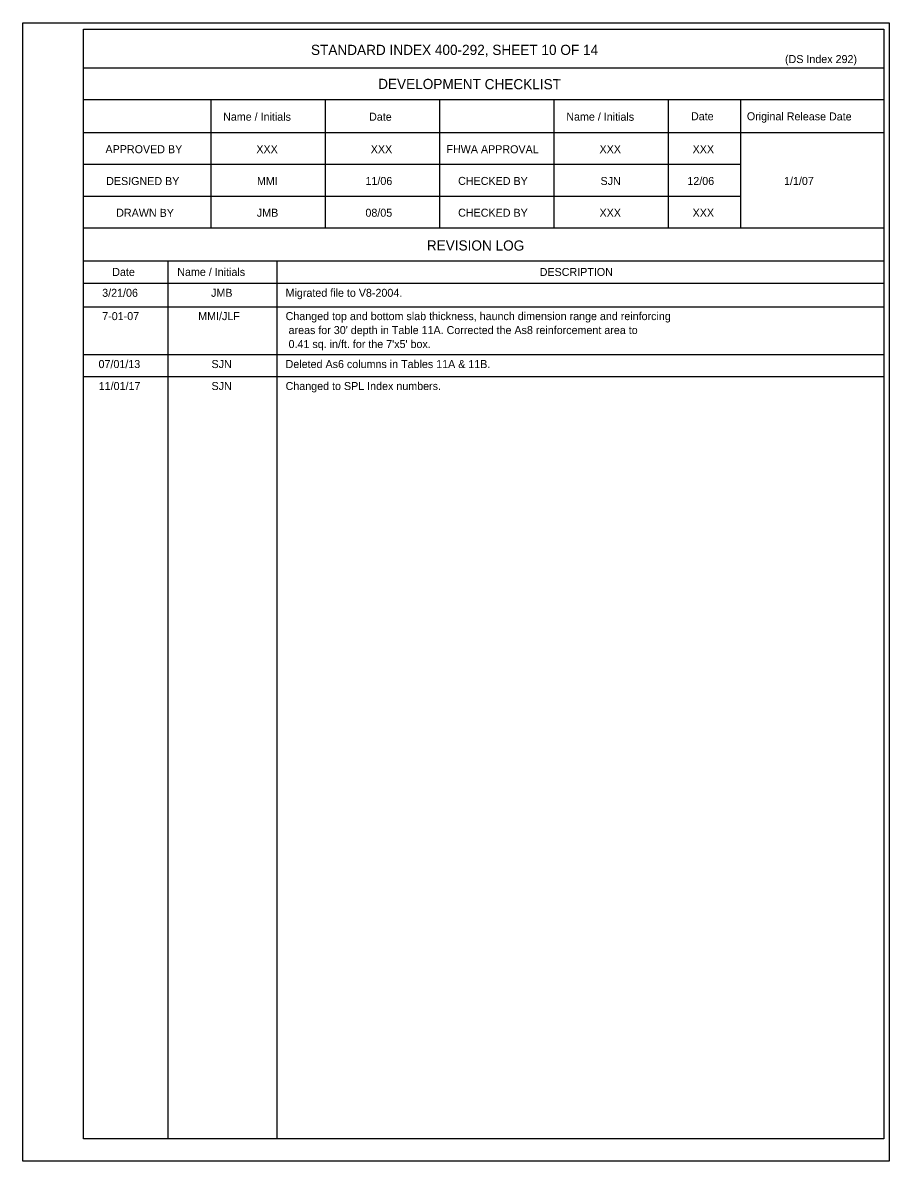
# Model space of a CAD drawing. Extents: x 10342.77 to 10344.98, y 76371.51 to 76372.62.
# Drawn here: x 10344.301 to 10344.983, y 76371.667 to 76372.563 of the extents above; entities that cross this region are included whole.
import ezdxf

# ---------------------------------------------------------------- set-up
doc = ezdxf.new("R2010")
doc.units = 0
for name, color, linetype in [('AdhocPoint_dp', 7, 'Continuous'), ('Border', 7, 'Continuous'), ('PlotBorder_dp', 7, 'Continuous')]:
    doc.layers.add(name, color=color, linetype=linetype)

msp = doc.modelspace()

# ---------------------------------------------------------------- linework, layer by layer
at = {"layer": 'Border'}
for p, q in [((10344.97841, 76372.52706), (10344.34883, 76372.52706)), ((10344.97841, 76372.50206), (10344.34883, 76372.50206)), ((10344.44883, 76372.50206), (10344.44883, 76372.40119)), ((10344.53883, 76372.50206), (10344.53883, 76372.40119)), ((10344.62883, 76372.50206), (10344.62883, 76372.40119)), ((10344.71883, 76372.50206), (10344.71883, 76372.40119)), ((10344.80883, 76372.50206), (10344.80883, 76372.40119)), ((10344.86554, 76372.50206), (10344.86554, 76372.40119)), ((10344.97841, 76372.47619), (10344.34883, 76372.47619)), ((10344.86554, 76372.45119), (10344.34883, 76372.45119)), ((10344.86554, 76372.42619), (10344.34883, 76372.42619)), ((10344.97841, 76372.40119), (10344.34883, 76372.40119)), ((10344.97841, 76372.37532), (10344.34883, 76372.37532)), ((10344.41509, 76372.37532), (10344.41509, 76371.68449)), ((10344.50078, 76372.37532), (10344.50078, 76371.68449)), ((10344.97841, 76372.3577), (10344.34883, 76372.3577)), ((10344.301, 76371.66695), (10344.301, 76371.66695))]:
    msp.add_line(p, q, dxfattribs=at)
for points in [[(10344.301, 76372.56278), (10344.98267, 76372.56278), (10344.98267, 76371.66695), (10344.301, 76371.66695)], [(10344.34884, 76372.5577), (10344.97841, 76372.5577), (10344.97841, 76371.68449), (10344.34884, 76371.68449)]]:
    msp.add_lwpolyline(points, close=True, dxfattribs=at)
at = {"layer": 'PlotBorder_dp'}
for p, q in [((10344.34884, 76372.33937), (10344.97841, 76372.33937)), ((10344.34884, 76372.30164), (10344.97841, 76372.30164)), ((10344.34884, 76372.28435), (10344.97841, 76372.28435))]:
    msp.add_line(p, q, dxfattribs=at)

# ---------------------------------------------------------------- texts
at = {"layer": 'AdhocPoint_dp'}
for s, height, p in [('STANDARD INDEX 400-292, SHEET 10 OF 14', 0.008, (10344.52773, 76372.53745)), ('(DS Index 292)', 0.0063, (10344.90067, 76372.53106)), ('XXX', 0.0063, (10344.48477, 76372.46015)), ('XXX', 0.0063, (10344.57477, 76372.46015)), ('XXX', 0.0063, (10344.75476, 76372.46015)), ('XXX', 0.0063, (10344.82799, 76372.46015)), ('MMI', 0.0063, (10344.48526, 76372.43515)), ('11/06', 0.0063, (10344.57062, 76372.43515)), ('SJN', 0.0063, (10344.75553, 76372.43515)), ('12/06', 0.0063, (10344.82385, 76372.43515)), ('1/1/07', 0.0063, (10344.89992, 76372.43515)), ('JMB', 0.0063, (10344.48517, 76372.41015)), ('08/05', 0.0063, (10344.57058, 76372.41015)), ('XXX', 0.0063, (10344.75476, 76372.41015)), ('XXX', 0.0063, (10344.82799, 76372.41015)), ('DESCRIPTION', 0.0063, (10344.70769, 76372.36354)), ('3/21/06', 0.0063, (10344.36349, 76372.34714)), ('JMB', 0.0063, (10344.44913, 76372.34714)), ('Migrated file to V8-2004.', 0.0063, (10344.50777, 76372.34714)), ('MMI/JLF', 0.0063, (10344.439, 76372.3288)), ('Changed top and bottom slab thickness, haunch dimension range and reinforcing ', 0.0063, (10344.50778, 76372.3288)), ('7-01-07', 0.0063, (10344.36351, 76372.3288)), (" areas for 30' depth in Table 11A. Corrected the As8 reinforcement area to ", 0.0063, (10344.50778, 76372.31782)), (" 0.41 sq. in/ft. for the 7'x5' box.", 0.0063, (10344.50778, 76372.30683)), ('07/01/13', 0.0063, (10344.3606, 76372.29108)), ('SJN', 0.0063, (10344.4495, 76372.29108)), ('Deleted As6 columns in Tables 11A & 11B.', 0.0063, (10344.50778, 76372.29108)), ('11/01/17', 0.0063, (10344.36075, 76372.27379)), ('SJN', 0.0063, (10344.4495, 76372.27379)), ('Changed to SPL Index numbers.', 0.0063, (10344.50778, 76372.27379))]:
    msp.add_text(s, height=height, dxfattribs=at).set_placement(p)
for s, height, p in [('DEVELOPMENT CHECKLIST', 0.008, (10344.58057, 76372.51071)), ('Name / Initials', 0.0063, (10344.4586, 76372.48578)), ('Date', 0.0063, (10344.57343, 76372.48573)), ('Name / Initials', 0.0063, (10344.7286, 76372.48578)), ('Date', 0.0063, (10344.82671, 76372.48609)), ('Original Release Date', 0.0063, (10344.87066, 76372.48608)), ('APPROVED BY', 0.0063, (10344.36607, 76372.46021)), ('FHWA APPROVAL', 0.0063, (10344.6343, 76372.46021)), ('DESIGNED BY', 0.0063, (10344.3666, 76372.43515)), ('CHECKED BY', 0.0063, (10344.64351, 76372.43521)), ('DRAWN BY', 0.0063, (10344.3745, 76372.41015)), ('CHECKED BY', 0.0063, (10344.64351, 76372.41021)), ('REVISION LOG', 0.008, (10344.61886, 76372.38365)), ('Date', 0.0063, (10344.3714, 76372.36356)), ('Name / Initials', 0.0063, (10344.42254, 76372.36361))]:
    msp.add_text(s, height=height, rotation=359.87563, dxfattribs=at).set_placement(p)

doc.saveas('drawing.dxf')
